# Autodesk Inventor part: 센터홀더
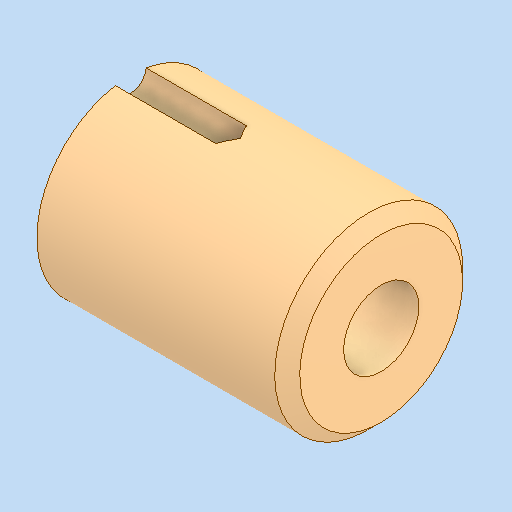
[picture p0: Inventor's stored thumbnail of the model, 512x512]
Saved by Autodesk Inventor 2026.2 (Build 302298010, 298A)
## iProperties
Created: 2026-08
Part Number: 센터홀더
Material: 강철, 연강
Document SubType Name: Modeling
Designer: PC-2-06
Density: 7.86 g/cm^3
Appearance: 기본값
Author: jhkim
Sending System: Autodesk Inventor 2027
Preprocessor: ST-DEVELOPER v20.1
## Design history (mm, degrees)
feature "솔리드1"
node "솔리드2"
